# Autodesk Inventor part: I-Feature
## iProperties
Created: 2006-07
Part Number: I-Feature
Document SubType Name: Modeling
Designer: xxs
Author: xxs
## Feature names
1. Drehung1 [Revolution]
2. Drehung2 [Revolution]
